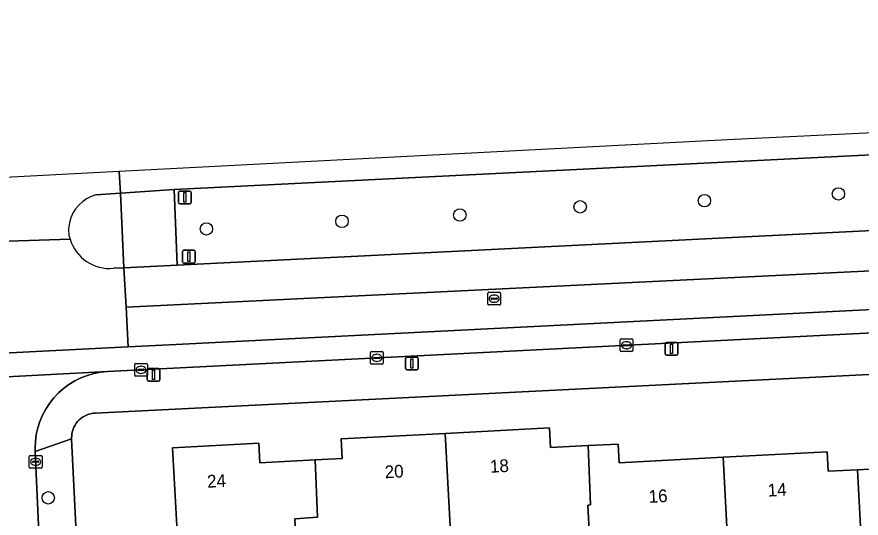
# Model space of a CAD drawing. Extents: x 161248 to 161848, y 384871 to 385383.
# Drawn here: x 161394.3 to 161460.7, y 385331.7 to 385371.1 of the extents above; entities that cross this region are included whole.
import ezdxf

# ---------------------------------------------------------------- set-up
doc = ezdxf.new("R2010")
doc.units = 0
for name, color, linetype in [('IMGEO_Berm_groen', 7, 'Continuous'), ('IMGEO_Boom', 7, 'Continuous'), ('IMGEO_Erf', 7, 'Continuous'), ('IMGEO_Kolk', 7, 'Continuous'), ('IMGEO_Lichtmast', 7, 'Continuous'), ('IMGEO_Pand', 7, 'Continuous'), ('IMGEO_Pand_nummerreeks', 7, 'Continuous'), ('IMGEO_Rijbaan_lokaal_gesloten', 7, 'Continuous'), ('IMGEO_Rijbaan_lokaal_open', 7, 'Continuous'), ('IMGEO_Rijbaan_regionaal_gesloten', 7, 'Continuous'), ('IMGEO_Rioolput', 7, 'Continuous'), ('IMGEO_Verkeersbordpaal', 7, 'Continuous'), ('IMGEO_Verkeerseiland_open', 7, 'Continuous'), ('IMGEO_Voetpad_open', 7, 'Continuous')]:
    doc.layers.add(name, color=color, linetype=linetype)

msp = doc.modelspace()

# ---------------------------------------------------------------- linework, layer by layer
at = {"layer": 'IMGEO_Berm_groen'}
msp.add_lwpolyline([(161537.971, 385358.117), (161537.631, 385364.146), (161512.938, 385362.801), (161500, 385362.16), (161406.661, 385357.501), (161406.917, 385351.557), (161500, 385356.205)], close=True, dxfattribs=at)
at = {"layer": 'IMGEO_Boom'}
for centre in [(161458.917, 385357.158), (161438.602, 385356.144), (161448.38, 385356.632), (161429.142, 385355.503), (161419.873, 385355.006), (161409.205, 385354.406), (161396.765, 385333.248)]:
    msp.add_circle(centre, 0.489, dxfattribs=at)
at = {"layer": 'IMGEO_Erf'}
for points in [[(161470.763, 385343.422), (161400.445, 385339.917), (161400.272, 385339.9), (161400.101, 385339.868), (161399.933, 385339.821), (161399.771, 385339.759), (161399.615, 385339.683), (161399.466, 385339.593), (161399.325, 385339.491), (161399.195, 385339.376), (161399.075, 385339.25), (161398.967, 385339.113), (161398.871, 385338.968), (161398.789, 385338.815), (161398.721, 385338.654), (161398.668, 385338.489), (161398.629, 385338.319), (161398.606, 385338.147), (161398.599, 385337.973), (161398.601, 385337.878), (161399.745, 385314.686)], [(161406.945, 385329.635), (161406.547, 385337.179), (161413.324, 385337.537), (161413.405, 385336.002), (161417.772, 385336.233), (161419.889, 385336.345), (161419.808, 385337.885), (161427.998, 385338.318), (161436.186, 385338.75), (161436.268, 385337.196), (161439.246, 385337.353), (161441.604, 385337.478), (161441.682, 385336.008), (161449.852, 385336.44), (161458.025, 385336.872), (161458.106, 385335.342), (161460.417, 385335.464), (161462.729, 385335.586)]]:
    msp.add_lwpolyline(points, dxfattribs=at)
at = {"layer": 'IMGEO_Kolk'}
for p, q in [((161441.752, 385344.828), (161441.752, 385345.68)), ((161441.827, 385345.754), (161442.679, 385345.754)), ((161442.054, 385345.297), (161442.452, 385345.297)), ((161442.24, 385345.534), (161442.265, 385345.534)), ((161442.753, 385345.68), (161442.753, 385344.828)), ((161422.108, 385343.833), (161422.108, 385344.685)), ((161422.183, 385344.759), (161423.035, 385344.759)), ((161423.109, 385344.685), (161423.109, 385343.833)), ((161442.679, 385344.754), (161441.827, 385344.754)), ((161442.011, 385345.248), (161442.011, 385345.26)), ((161442.449, 385345.211), (161442.051, 385345.211)), ((161442.263, 385344.974), (161442.238, 385344.974)), ((161442.495, 385345.26), (161442.495, 385345.248)), ((161422.367, 385344.253), (161422.367, 385344.265)), ((161422.805, 385344.216), (161422.407, 385344.216)), ((161422.41, 385344.302), (161422.808, 385344.302)), ((161422.619, 385343.979), (161422.594, 385343.979)), ((161422.596, 385344.539), (161422.621, 385344.539)), ((161422.851, 385344.265), (161422.851, 385344.253)), ((161403.563, 385342.891), (161403.563, 385343.743)), ((161403.638, 385343.817), (161404.49, 385343.817)), ((161403.822, 385343.311), (161403.822, 385343.323)), ((161403.865, 385343.36), (161404.263, 385343.36)), ((161404.051, 385343.597), (161404.076, 385343.597)), ((161404.306, 385343.323), (161404.306, 385343.311)), ((161404.564, 385343.743), (161404.564, 385342.891)), ((161423.035, 385343.759), (161422.183, 385343.759)), ((161404.49, 385342.817), (161403.638, 385342.817)), ((161404.26, 385343.274), (161403.862, 385343.274)), ((161404.074, 385343.037), (161404.049, 385343.037)), ((161395.273, 385335.659), (161395.273, 385336.511)), ((161395.348, 385336.585), (161396.2, 385336.585)), ((161395.532, 385336.079), (161395.532, 385336.091)), ((161395.97, 385336.042), (161395.572, 385336.042)), ((161395.575, 385336.128), (161395.973, 385336.128)), ((161395.761, 385336.365), (161395.786, 385336.365)), ((161396.016, 385336.091), (161396.016, 385336.079)), ((161396.274, 385336.511), (161396.274, 385335.659)), ((161396.2, 385335.585), (161395.348, 385335.585)), ((161395.784, 385335.805), (161395.759, 385335.805))]:
    msp.add_line(p, q, dxfattribs=at)
for points in [[(161441.752, 385344.828), (161441.752, 385345.68)], [(161441.827, 385345.754), (161442.679, 385345.754)], [(161442.753, 385345.68), (161442.753, 385344.828)], [(161422.108, 385343.833), (161422.108, 385344.685)], [(161422.183, 385344.759), (161423.035, 385344.759)], [(161423.109, 385344.685), (161423.109, 385343.833)], [(161442.679, 385344.754), (161441.827, 385344.754)], [(161403.563, 385342.891), (161403.563, 385343.743)], [(161403.638, 385343.817), (161404.49, 385343.817)], [(161404.564, 385343.743), (161404.564, 385342.891)], [(161423.035, 385343.759), (161422.183, 385343.759)], [(161404.49, 385342.817), (161403.638, 385342.817)], [(161395.273, 385335.659), (161395.273, 385336.511)], [(161395.348, 385336.585), (161396.2, 385336.585)], [(161396.274, 385336.511), (161396.274, 385335.659)], [(161396.2, 385335.585), (161395.348, 385335.585)]]:
    msp.add_lwpolyline(points, dxfattribs=at)
for centre, radius, start, end in [((161441.829, 385345.678), 0.0765, 91.55205, 178.44795), ((161441.829, 385345.678), 0.0765, 91.55205, 178.44795), ((161442.051, 385345.257), 0.0403, 85.87752, 175.75265), ((161442.456, 385345.259), 0.0386, 1.73085, 96.63898), ((161442.677, 385345.678), 0.0765, 1.55205, 88.44795), ((161442.677, 385345.678), 0.0765, 1.55205, 88.44795), ((161422.185, 385344.683), 0.0765, 91.55205, 178.44795), ((161422.185, 385344.683), 0.0765, 91.55205, 178.44795), ((161423.033, 385344.683), 0.0765, 1.55205, 88.44795), ((161423.033, 385344.683), 0.0765, 1.55205, 88.44795), ((161441.829, 385344.83), 0.0765, 181.55205, 268.44795), ((161441.829, 385344.83), 0.0765, 181.55205, 268.44795), ((161442.048, 385345.247), 0.0366, 178.93798, 274.71019), ((161442.452, 385345.254), 0.043, 264.86636, 352.45326), ((161442.677, 385344.83), 0.0765, 271.55205, 358.44795), ((161442.677, 385344.83), 0.0765, 271.55205, 358.44795), ((161422.407, 385344.262), 0.0403, 85.87752, 175.75265), ((161422.404, 385344.252), 0.0366, 178.93798, 274.71019), ((161422.808, 385344.259), 0.043, 264.86636, 352.45326), ((161422.812, 385344.264), 0.0386, 1.73085, 96.63898), ((161403.64, 385343.741), 0.0765, 91.55205, 178.44795), ((161403.64, 385343.741), 0.0765, 91.55205, 178.44795), ((161403.862, 385343.32), 0.0403, 85.87752, 175.75265), ((161403.859, 385343.31), 0.0366, 178.93798, 274.71019), ((161404.263, 385343.317), 0.043, 264.86636, 352.45326), ((161404.267, 385343.322), 0.0386, 1.73085, 96.63898), ((161404.488, 385343.741), 0.0765, 1.55205, 88.44795), ((161404.488, 385343.741), 0.0765, 1.55205, 88.44795), ((161422.185, 385343.835), 0.0765, 181.55205, 268.44795), ((161422.185, 385343.835), 0.0765, 181.55205, 268.44795), ((161423.033, 385343.835), 0.0765, 271.55205, 358.44795), ((161423.033, 385343.835), 0.0765, 271.55205, 358.44795), ((161403.64, 385342.893), 0.0765, 181.55205, 268.44795), ((161403.64, 385342.893), 0.0765, 181.55205, 268.44795), ((161404.488, 385342.893), 0.0765, 271.55205, 358.44795), ((161404.488, 385342.893), 0.0765, 271.55205, 358.44795), ((161395.35, 385336.509), 0.0765, 91.55205, 178.44795), ((161395.35, 385336.509), 0.0765, 91.55205, 178.44795), ((161395.572, 385336.088), 0.0403, 85.87752, 175.75265), ((161395.569, 385336.078), 0.0366, 178.93798, 274.71019), ((161395.973, 385336.085), 0.043, 264.86636, 352.45326), ((161395.977, 385336.09), 0.0386, 1.73085, 96.63898), ((161396.198, 385336.509), 0.0765, 1.55205, 88.44795), ((161396.198, 385336.509), 0.0765, 1.55205, 88.44795), ((161395.35, 385335.661), 0.0765, 181.55205, 268.44795), ((161395.35, 385335.661), 0.0765, 181.55205, 268.44795), ((161396.198, 385335.661), 0.0765, 271.55205, 358.44795), ((161396.198, 385335.661), 0.0765, 271.55205, 358.44795)]:
    msp.add_arc(centre, radius, start, end, dxfattribs=at)
for centre, major_axis, ratio, start_param, end_param in [((161442.239, 385345.254), (-0.387, 0.002), 0.722429, 4.712389, 7.853982), ((161442.264, 385345.254), (-0.39, 0.002), 0.717154, 1.570796, 4.712389), ((161422.595, 385344.259), (-0.387, 0.002), 0.722429, 4.712389, 7.853982), ((161422.62, 385344.259), (-0.39, 0.002), 0.717154, 1.570796, 4.712389), ((161404.05, 385343.317), (-0.387, 0.002), 0.722429, 4.712389, 7.853982), ((161404.075, 385343.317), (-0.39, 0.002), 0.717154, 1.570796, 4.712389), ((161395.76, 385336.085), (-0.387, 0.002), 0.722429, 4.712389, 7.853982), ((161395.785, 385336.085), (-0.39, 0.002), 0.717154, 1.570796, 4.712389)]:
    msp.add_ellipse(centre, major_axis=major_axis, ratio=ratio, start_param=start_param, end_param=end_param, dxfattribs=at)
at = {"layer": 'IMGEO_Lichtmast'}
for p, q in [((161445.288, 385344.574), (161445.288, 385345.374)), ((161445.288, 385345.374), (161445.288, 385344.574)), ((161445.388, 385345.474), (161446.178, 385345.474)), ((161446.178, 385345.474), (161445.388, 385345.474)), ((161446.278, 385345.374), (161446.278, 385344.574)), ((161446.278, 385344.574), (161446.278, 385345.374)), ((161424.877, 385343.415), (161424.877, 385344.215)), ((161424.877, 385344.215), (161424.877, 385343.415)), ((161424.977, 385344.315), (161425.767, 385344.315)), ((161425.767, 385344.315), (161424.977, 385344.315)), ((161425.867, 385344.215), (161425.867, 385343.415)), ((161425.867, 385343.415), (161425.867, 385344.215)), ((161446.178, 385344.474), (161445.388, 385344.474)), ((161445.388, 385344.474), (161446.178, 385344.474)), ((161404.556, 385342.523), (161404.556, 385343.323)), ((161404.556, 385343.323), (161404.556, 385342.523)), ((161404.656, 385343.423), (161405.446, 385343.423)), ((161405.446, 385343.423), (161404.656, 385343.423)), ((161405.546, 385343.323), (161405.546, 385342.523)), ((161405.546, 385342.523), (161405.546, 385343.323)), ((161425.767, 385343.315), (161424.977, 385343.315)), ((161424.977, 385343.315), (161425.767, 385343.315)), ((161405.446, 385342.423), (161404.656, 385342.423)), ((161404.656, 385342.423), (161405.446, 385342.423))]:
    msp.add_line(p, q, dxfattribs=at)
for points in [[(161445.708, 385345.349), (161445.858, 385345.349), (161445.858, 385344.599), (161445.708, 385344.599), (161445.708, 385345.349)], [(161425.297, 385344.19), (161425.447, 385344.19), (161425.447, 385343.44), (161425.297, 385343.44), (161425.297, 385344.19)], [(161404.976, 385343.298), (161405.126, 385343.298), (161405.126, 385342.548), (161404.976, 385342.548), (161404.976, 385343.298)]]:
    msp.add_lwpolyline(points, dxfattribs=at)
for centre, start, end in [((161445.388, 385345.374), 90, 180), ((161445.388, 385345.374), 90, 180), ((161446.178, 385345.374), 0, 90), ((161446.178, 385345.374), 360, 90), ((161424.977, 385344.215), 90, 180), ((161424.977, 385344.215), 90, 180), ((161425.767, 385344.215), 0, 90), ((161425.767, 385344.215), 360, 90), ((161445.388, 385344.574), 180, 270), ((161445.388, 385344.574), 180, 270), ((161446.178, 385344.574), 270, 0), ((161446.178, 385344.574), 270, 0), ((161404.656, 385343.323), 90, 180), ((161404.656, 385343.323), 90, 180), ((161405.446, 385343.323), 0, 90), ((161405.446, 385343.323), 360, 90), ((161424.977, 385343.415), 180, 270), ((161424.977, 385343.415), 180, 270), ((161425.767, 385343.415), 270, 0), ((161425.767, 385343.415), 270, 0), ((161404.656, 385342.523), 180, 270), ((161404.656, 385342.523), 180, 270), ((161405.446, 385342.523), 270, 0), ((161405.446, 385342.523), 270, 0)]:
    msp.add_arc(centre, 0.1, start, end, dxfattribs=at)
at = {"layer": 'IMGEO_Pand'}
for points in [[(161429.025, 385318.867), (161433.614, 385319.103), (161433.064, 385329.823), (161437.765, 385330.065), (161439.338, 385330.146), (161439.208, 385332.681), (161439.416, 385332.689), (161439.246, 385337.353), (161436.268, 385337.196), (161436.186, 385338.75), (161427.998, 385338.318)], [(161427.998, 385338.318), (161419.808, 385337.885), (161419.889, 385336.345), (161417.772, 385336.233), (161417.951, 385331.733), (161416.162, 385331.603), (161416.302, 385328.911), (161423.98, 385329.306), (161424.53, 385318.636), (161425.276, 385318.674), (161428.76, 385318.853), (161429.025, 385318.867)], [(161413.405, 385336.002), (161413.324, 385337.537), (161406.547, 385337.179), (161406.945, 385329.635), (161403.906, 385329.475), (161404.511, 385318.31), (161410.531, 385318.619), (161410.366, 385321.824), (161415.587, 385322.128), (161415.383, 385325.643), (161416.466, 385325.699), (161416.302, 385328.911), (161416.162, 385331.603), (161417.951, 385331.733), (161417.772, 385336.233)], [(161449.852, 385336.44), (161441.682, 385336.008), (161441.604, 385337.478), (161439.246, 385337.353), (161439.416, 385332.689), (161439.208, 385332.681), (161439.338, 385330.146), (161441.471, 385330.256), (161441.792, 385324.014), (161441.934, 385321.258), (161450.323, 385321.69), (161450.181, 385324.445), (161450.482, 385324.46)], [(161471.521, 385328.179), (161471.073, 385337.452), (161462.654, 385337.007), (161462.729, 385335.586), (161460.417, 385335.464), (161460.681, 385330.484), (161462.922, 385330.599), (161463.231, 385324.606), (161471.673, 385325.04)], [(161458.294, 385330.361), (161460.681, 385330.484), (161460.417, 385335.464), (161458.106, 385335.342), (161458.025, 385336.872), (161449.852, 385336.44), (161450.482, 385324.46), (161458.576, 385324.877)]]:
    msp.add_lwpolyline(points, close=True, dxfattribs=at)
at = {"layer": 'IMGEO_Rijbaan_lokaal_gesloten'}
for points in [[(161402.333, 385358.921), (161402.436, 385357.21), (161406.661, 385357.501), (161500, 385362.16), (161512.938, 385362.801), (161537.631, 385364.146), (161539.104, 385364.226), (161611.671, 385367.796), (161626.526, 385371.088), (161625.733, 385371.057), (161621.627, 385370.918), (161611.523, 385369.168), (161450.189, 385361.402)], [(161631.227, 385360.108), (161604.148, 385358.631), (161563.952, 385356.122), (161510.999, 385353.531), (161402.887, 385348.241), (161403.061, 385345.136), (161405.743, 385345.272), (161538.32, 385351.908), (161617.266, 385356.241), (161631.397, 385356.891), (161631.252, 385359.649)]]:
    msp.add_lwpolyline(points, close=True, dxfattribs=at)
for points in [[(161402.333, 385358.921), (161391.347, 385358.351), (161384.19, 385357.98)], [(161400.515, 385357.078), (161402.436, 385357.21), (161402.333, 385358.921)], [(161382.607, 385342.195), (161401.421, 385343.184), (161500, 385348.169), (161538.421, 385350.118), (161631.519, 385354.842), (161631.397, 385356.891), (161617.266, 385356.241), (161538.32, 385351.908), (161405.743, 385345.272), (161403.061, 385345.136), (161313.081, 385340.569), (161302.699, 385339.685), (161293.531, 385337.916), (161290.897, 385337.069), (161291.775, 385334.722), (161292.828, 385335.119)], [(161384.421, 385357.171), (161384.594, 385353.158), (161398.476, 385353.605)], [(161398.476, 385353.605), (161384.594, 385353.158)], [(161290.897, 385337.069), (161293.531, 385337.916), (161302.699, 385339.685), (161313.081, 385340.569), (161403.061, 385345.136), (161402.887, 385348.241), (161402.713, 385351.347)], [(161402.713, 385351.347), (161401.897, 385351.306)]]:
    msp.add_lwpolyline(points, dxfattribs=at)
for centre, radius, start, end in [((161401.217, 385354.336), 2.831, 104.36733, 168.87825), ((161400.533, 385354.302), 2.172, 164.5148, 198.7148), ((161401.606, 385354.568), 3.275, 197.09475, 275.10102)]:
    msp.add_arc(centre, radius, start, end, dxfattribs=at)
at = {"layer": 'IMGEO_Rijbaan_lokaal_open'}
msp.add_lwpolyline([(161396.614, 385317.218), (161395.736, 385336.901), (161395.73, 385337.152), (161395.752, 385337.69), (161395.822, 385338.223), (161395.939, 385338.748), (161396.102, 385339.261), (161396.311, 385339.757), (161396.563, 385340.232), (161396.857, 385340.683), (161397.19, 385341.105), (161397.559, 385341.497), (161397.962, 385341.854), (161398.395, 385342.173), (161398.855, 385342.452), (161399.338, 385342.69), (161399.84, 385342.883), (161400.357, 385343.03), (161400.886, 385343.131), (161401.421, 385343.184), (161382.607, 385342.195)], dxfattribs=at)
at = {"layer": 'IMGEO_Rijbaan_regionaal_gesloten'}
msp.add_lwpolyline([(161631.085, 385362.806), (161626.952, 385362.598), (161537.971, 385358.117), (161500, 385356.205), (161406.917, 385351.557), (161402.713, 385351.347), (161402.887, 385348.241), (161510.999, 385353.531), (161563.952, 385356.122), (161604.148, 385358.631), (161631.227, 385360.108)], close=True, dxfattribs=at)
at = {"layer": 'IMGEO_Rioolput'}
for p, q in [((161431.335, 385348.495), (161431.335, 385349.347)), ((161431.41, 385349.421), (161432.262, 385349.421)), ((161432.336, 385349.347), (161432.336, 385348.495)), ((161431.594, 385348.915), (161431.594, 385348.927)), ((161432.032, 385348.878), (161431.634, 385348.878)), ((161431.637, 385348.964), (161432.035, 385348.964)), ((161431.846, 385348.641), (161431.821, 385348.641)), ((161431.823, 385349.201), (161431.848, 385349.201)), ((161432.078, 385348.927), (161432.078, 385348.915)), ((161432.262, 385348.421), (161431.41, 385348.421))]:
    msp.add_line(p, q, dxfattribs=at)
for points in [[(161431.335, 385348.495), (161431.335, 385349.347)], [(161431.41, 385349.421), (161432.262, 385349.421)], [(161432.336, 385349.347), (161432.336, 385348.495)], [(161432.262, 385348.421), (161431.41, 385348.421)]]:
    msp.add_lwpolyline(points, dxfattribs=at)
for centre, radius, start, end in [((161431.412, 385349.345), 0.0765, 91.55205, 178.44795), ((161431.412, 385349.345), 0.0765, 91.55205, 178.44795), ((161432.26, 385349.345), 0.0765, 1.55205, 88.44795), ((161432.26, 385349.345), 0.0765, 1.55205, 88.44795), ((161431.634, 385348.924), 0.0403, 85.87752, 175.75265), ((161431.631, 385348.914), 0.0366, 178.93798, 274.71019), ((161432.035, 385348.921), 0.043, 264.86636, 352.45326), ((161432.039, 385348.926), 0.0386, 1.73085, 96.63898), ((161431.412, 385348.497), 0.0765, 181.55205, 268.44795), ((161431.412, 385348.497), 0.0765, 181.55205, 268.44795), ((161432.26, 385348.497), 0.0765, 271.55205, 358.44795), ((161432.26, 385348.497), 0.0765, 271.55205, 358.44795)]:
    msp.add_arc(centre, radius, start, end, dxfattribs=at)
for centre, major_axis, ratio, start_param, end_param in [((161431.822, 385348.921), (-0.387, 0.002), 0.722429, 4.712389, 7.853982), ((161431.847, 385348.921), (-0.39, 0.002), 0.717154, 1.570796, 4.712389)]:
    msp.add_ellipse(centre, major_axis=major_axis, ratio=ratio, start_param=start_param, end_param=end_param, dxfattribs=at)
at = {"layer": 'IMGEO_Verkeersbordpaal'}
for p, q in [((161407.015, 385356.483), (161407.015, 385357.283)), ((161407.015, 385357.283), (161407.015, 385356.483)), ((161407.115, 385357.383), (161407.905, 385357.383)), ((161407.905, 385357.383), (161407.115, 385357.383)), ((161408.005, 385357.283), (161408.005, 385356.483)), ((161408.005, 385356.483), (161408.005, 385357.283)), ((161407.905, 385356.383), (161407.115, 385356.383)), ((161407.115, 385356.383), (161407.905, 385356.383)), ((161407.331, 385351.822), (161407.331, 385352.622)), ((161407.331, 385352.622), (161407.331, 385351.822)), ((161407.431, 385352.722), (161408.221, 385352.722)), ((161408.221, 385352.722), (161407.431, 385352.722)), ((161408.321, 385352.622), (161408.321, 385351.822)), ((161408.321, 385351.822), (161408.321, 385352.622)), ((161408.221, 385351.722), (161407.431, 385351.722)), ((161407.431, 385351.722), (161408.221, 385351.722))]:
    msp.add_line(p, q, dxfattribs=at)
for points in [[(161407.435, 385357.258), (161407.585, 385357.258), (161407.585, 385356.508), (161407.435, 385356.508), (161407.435, 385357.258)], [(161407.751, 385352.597), (161407.901, 385352.597), (161407.901, 385351.847), (161407.751, 385351.847), (161407.751, 385352.597)]]:
    msp.add_lwpolyline(points, dxfattribs=at)
for centre, start, end in [((161407.115, 385357.283), 90, 180), ((161407.115, 385357.283), 90, 180), ((161407.905, 385357.283), 0, 90), ((161407.905, 385357.283), 360, 90), ((161407.115, 385356.483), 180, 270), ((161407.115, 385356.483), 180, 270), ((161407.905, 385356.483), 270, 0), ((161407.905, 385356.483), 270, 0), ((161407.431, 385352.622), 90, 180), ((161407.431, 385352.622), 90, 180), ((161408.221, 385352.622), 0, 90), ((161408.221, 385352.622), 360, 90), ((161407.431, 385351.822), 180, 270), ((161407.431, 385351.822), 180, 270), ((161408.221, 385351.822), 270, 0), ((161408.221, 385351.822), 270, 0)]:
    msp.add_arc(centre, 0.1, start, end, dxfattribs=at)
at = {"layer": 'IMGEO_Verkeerseiland_open'}
msp.add_lwpolyline([(161401.897, 385351.306), (161402.713, 385351.347), (161402.436, 385357.21), (161400.515, 385357.078)], dxfattribs=at)
for centre, radius, start, end in [((161401.217, 385354.336), 2.831, 104.36733, 168.87825), ((161400.533, 385354.302), 2.172, 164.5148, 198.7148), ((161401.606, 385354.568), 3.275, 197.09475, 275.10102)]:
    msp.add_arc(centre, radius, start, end, dxfattribs=at)
at = {"layer": 'IMGEO_Voetpad_open'}
msp.add_lwpolyline([(161402.436, 385357.21), (161402.713, 385351.347), (161406.917, 385351.557), (161406.661, 385357.501)], close=True, dxfattribs=at)
for points in [[(161500, 385348.169), (161401.421, 385343.184), (161400.886, 385343.131), (161400.357, 385343.03), (161399.84, 385342.883), (161399.338, 385342.69), (161398.855, 385342.452), (161398.395, 385342.173), (161397.962, 385341.854), (161397.559, 385341.497), (161397.19, 385341.105), (161396.857, 385340.683), (161396.563, 385340.232), (161396.311, 385339.757), (161396.102, 385339.261), (161395.939, 385338.748), (161395.822, 385338.223), (161395.752, 385337.69), (161395.73, 385337.152), (161395.736, 385336.901), (161398.601, 385337.878), (161398.599, 385337.973), (161398.606, 385338.147), (161398.629, 385338.319), (161398.668, 385338.489), (161398.721, 385338.654), (161398.789, 385338.815), (161398.871, 385338.968), (161398.967, 385339.113), (161399.075, 385339.25), (161399.195, 385339.376), (161399.325, 385339.491), (161399.466, 385339.593), (161399.615, 385339.683), (161399.771, 385339.759), (161399.933, 385339.821), (161400.101, 385339.868), (161400.272, 385339.9), (161400.445, 385339.917), (161470.763, 385343.422)], [(161400.097, 385307.562), (161399.745, 385314.686), (161398.601, 385337.878), (161395.736, 385336.901), (161396.614, 385317.218), (161396.664, 385316.508), (161396.675, 385315.878), (161396.609, 385314.509), (161396.42, 385313.152), (161396.112, 385311.817), (161395.685, 385310.515), (161395.144, 385309.256), (161394.868, 385308.726), (161394.178, 385307.586), (161393.388, 385306.512), (161392.505, 385305.512), (161391.537, 385304.596)]]:
    msp.add_lwpolyline(points, dxfattribs=at)

# ---------------------------------------------------------------- texts
at = {"layer": 'IMGEO_Pand_nummerreeks'}
for s, rotation, p in [('18', 3.02325, (161431.534, 385335.219)), ('20', 3.02522, (161423.254, 385334.783)), ('24', 3.02388, (161409.283, 385334.038)), ('14', 3.02622, (161453.378, 385333.341)), ('16', 3.02622, (161444.015, 385332.846))]:
    msp.add_text(s, height=1, rotation=rotation, dxfattribs=at).set_placement(p)

doc.saveas('drawing.dxf')
